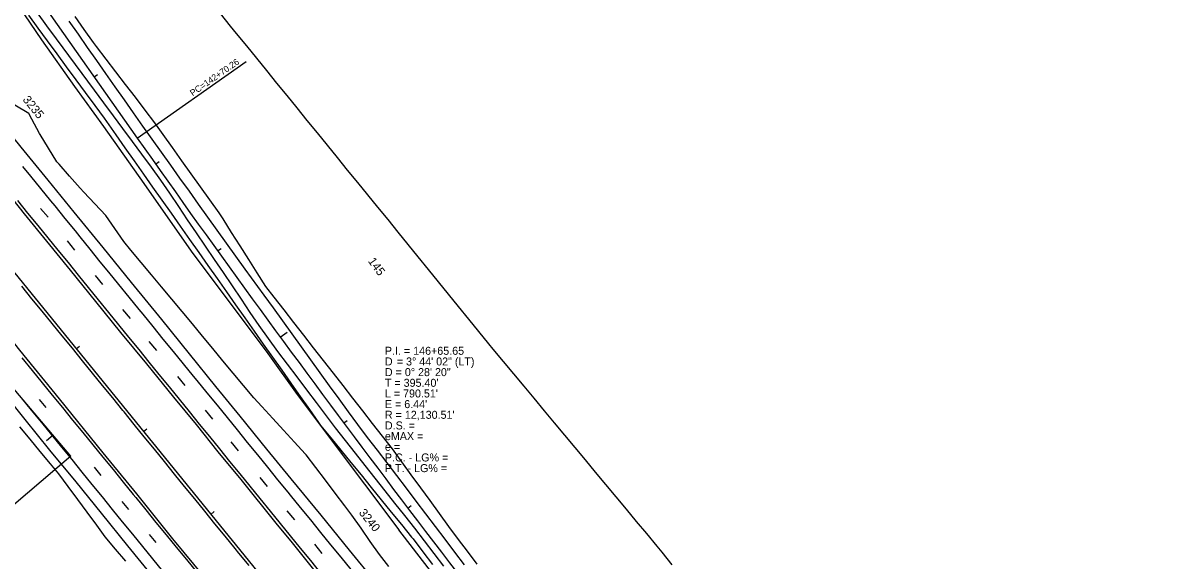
# Model space of a CAD drawing. Extents: x 2132221 to 2141942, y 535736 to 547298.
# Drawn here: x 2139996 to 2141080, y 538062 to 538566 of the extents above; entities that cross this region are included whole.
import ezdxf

# ---------------------------------------------------------------- set-up
doc = ezdxf.new("R2010")
doc.units = 0
for name, color, linetype in [('RD_EX_Driveway', 7, 'Continuous'), ('RD_EX_Fence_Other', 7, 'Continuous'), ('RD_EX_GuardRail', 7, 'Continuous'), ('RD_EX_Misc', 7, 'Continuous'), ('RD_EX_Road', 7, 'Continuous'), ('RD_EX_VEG', 7, 'Continuous'), ('RD_HC_Cl', 7, 'Continuous'), ('RD_HC_Data', 7, 'Continuous'), ('RD_HC_Data_Tic', 7, 'Continuous'), ('RD_HC_TX_Sta50', 7, 'Continuous'), ('TOPO_E_TLIML-Line', 7, 'Continuous')]:
    doc.layers.add(name, color=color, linetype=linetype)

msp = doc.modelspace()

# ---------------------------------------------------------------- linework, layer by layer
at = {"layer": 'RD_EX_Driveway'}
for points in [[(2140009.3, 538575.5), (2140018, 538563.3), (2140026.9, 538551.3), (2140062.6, 538503.2), (2140071.5, 538491.1), (2140080.4, 538479.1), (2140089.3, 538467.1), (2140098.2, 538455), (2140107.1, 538443), (2140116, 538431), (2140124.7, 538418.8), (2140133.1, 538406.4), (2140141.5, 538394), (2140149.9, 538381.6), (2140158.2, 538369.2), (2140175, 538344.4), (2140183.4, 538332), (2140191.8, 538319.6), (2140200.2, 538307.2), (2140208.6, 538294.8), (2140217, 538282.4), (2140225.5, 538270.2), (2140234.5, 538258.2), (2140243.5, 538246.3), (2140252.5, 538234.3), (2140261.5, 538222.3), (2140270.5, 538210.4), (2140288.5, 538186.5), (2140297.7, 538174.6), (2140307, 538162.9), (2140316.3, 538151.1), (2140325.5, 538139.4), (2140334.8, 538127.6), (2140344.1, 538115.9), (2140353.3, 538104.2), (2140362.6, 538092.4), (2140371.9, 538080.6), (2140380.9, 538068.7), (2140390, 538056.8)], [(2140409.6, 538058.2), (2140400.5, 538070.1), (2140391.4, 538082.1), (2140382.4, 538094), (2140373.3, 538106), (2140364.2, 538117.9), (2140355.1, 538129.8), (2140346.1, 538141.8), (2140337, 538153.7), (2140327.9, 538165.7), (2140318.8, 538177.6), (2140309.7, 538189.6), (2140300.8, 538201.6), (2140292, 538213.7), (2140283.2, 538225.9), (2140274.4, 538238.1), (2140265.7, 538250.2), (2140256.9, 538262.4), (2140248.1, 538274.6), (2140239.3, 538286.7), (2140230.6, 538298.9), (2140221.8, 538311), (2140204.2, 538335.4), (2140195.4, 538347.5), (2140186.7, 538359.7), (2140177.9, 538371.9), (2140169.2, 538384.1), (2140160.5, 538396.3), (2140151.8, 538408.5), (2140143, 538420.7), (2140134.3, 538432.9), (2140125.6, 538445.1), (2140116.9, 538457.3), (2140108.2, 538469.5), (2140099.5, 538481.8), (2140090.9, 538494), (2140082.3, 538506.3), (2140073.7, 538518.6), (2140065.1, 538530.9), (2140056.5, 538543.2), (2140047.9, 538555.5), (2140039.3, 538567.8)]]:
    msp.add_lwpolyline(points, dxfattribs=at)
at = {"layer": 'RD_EX_Fence_Other'}
msp.add_line((2140437, 537976), (2140348, 538090.8), dxfattribs=at)
for points in [[(2139980.7, 538598.3), (2140013.3, 538550.2), (2140044.2, 538506.6), (2140071.5, 538469), (2140109.3, 538415.7)], [(2140109.3, 538415.7), (2140153.5, 538352.1), (2140225.2, 538256.2)], [(2140225.2, 538256.2), (2140252.7, 538217.7), (2140316, 538133.7), (2140348, 538090.8)]]:
    msp.add_lwpolyline(points, dxfattribs=at)
at = {"layer": 'RD_EX_GuardRail'}
msp.add_lwpolyline([(2140207.8, 538057.3), (2140198.3, 538068.9), (2140194.6, 538073.3), (2140185.2, 538085), (2140175.7, 538096.6), (2140166.3, 538108.3), (2140156.8, 538119.9), (2140147.3, 538131.6), (2140137.9, 538143.2), (2140128.4, 538154.8), (2140119, 538166.5), (2140109.5, 538178.1), (2140100.1, 538189.8), (2140090.6, 538201.4), (2140089.4, 538202.8), (2140080, 538214.5), (2140070.5, 538226.1), (2140061.1, 538237.8), (2140051.6, 538249.4), (2140042.2, 538261.1), (2140032.7, 538272.7), (2140023.2, 538284.4), (2140013.8, 538296), (2140004.3, 538307.6), (2139994.9, 538319.3)], dxfattribs=at)
at = {"layer": 'RD_EX_Misc'}
for p, q in [((2140012.5, 538392.3), (2140019.5, 538383.9)), ((2140037.3, 538361.7), (2140044.3, 538353.2)), ((2140063.5, 538329.4), (2140070.5, 538320.9)), ((2140089.3, 538297.4), (2140096.3, 538289)), ((2140113.9, 538267.6), (2140121, 538259.1)), ((2140140.6, 538234.5), (2140147.6, 538226.1)), ((2140011.2, 538213), (2140017.5, 538205.5)), ((2140166.5, 538203.2), (2140173.6, 538194.8)), ((2140190.6, 538173.5), (2140197.6, 538165)), ((2140062.6, 538149.5), (2140068.9, 538141.9)), ((2140217.7, 538140.1), (2140224.7, 538131.6)), ((2140088.6, 538117.6), (2140094.8, 538110.1)), ((2140243.2, 538108.8), (2140250.2, 538100.3)), ((2140114.1, 538086.4), (2140120.4, 538078.9)), ((2140269, 538077.3), (2140276, 538068.8))]:
    msp.add_line(p, q, dxfattribs=at)
for points in [[(2139995.5, 538431.6), (2140002.9, 538422.5), (2140012.4, 538410.9), (2140021.8, 538399.2), (2140025.7, 538394.5), (2140035.2, 538382.9), (2140044.7, 538371.3), (2140049.2, 538365.6), (2140058.6, 538354), (2140068, 538342.3), (2140076, 538332.4), (2140085.5, 538320.8), (2140095, 538309.1), (2140104.5, 538297.5), (2140108.1, 538293.1), (2140117.6, 538281.4), (2140127.1, 538269.8), (2140136.6, 538258.2), (2140146.1, 538246.6), (2140155.5, 538235), (2140158.8, 538231), (2140168.2, 538219.4), (2140177.7, 538207.7), (2140187.2, 538196.1), (2140196.6, 538184.5), (2140206.1, 538172.8), (2140215.6, 538161.2), (2140225, 538149.5), (2140234.5, 538137.9), (2140244, 538126.3), (2140246.3, 538123.5), (2140255.7, 538111.8), (2140265.2, 538100.2), (2140274.7, 538088.5), (2140284.1, 538076.9), (2140293.6, 538065.3), (2140303.1, 538053.6)], [(2139990.9, 538399.6), (2140000.3, 538387.9), (2140009.8, 538376.3), (2140019.2, 538364.7), (2140028.7, 538353), (2140038.2, 538341.4), (2140047.6, 538329.7), (2140057.1, 538318.1), (2140066.5, 538306.4), (2140076, 538294.8), (2140085.5, 538283.2), (2140094.9, 538271.5), (2140104.4, 538259.9), (2140113.8, 538248.2), (2140123.3, 538236.6), (2140132.8, 538225), (2140142.2, 538213.3), (2140151.7, 538201.7), (2140161.1, 538190), (2140170.6, 538178.4), (2140180.1, 538166.8), (2140189.5, 538155.1), (2140199, 538143.5), (2140208.4, 538131.8), (2140217.9, 538120.2), (2140227.4, 538108.5), (2140236.8, 538096.9), (2140246.3, 538085.3), (2140255.7, 538073.6), (2140265.2, 538062), (2140274.7, 538050.3)], [(2139995, 538252), (2140004.5, 538240.4), (2140014, 538228.7), (2140023.4, 538217.1), (2140032.9, 538205.5), (2140042.4, 538193.8), (2140051.9, 538182.2), (2140061.3, 538170.6), (2140070.8, 538158.9), (2140080.3, 538147.3), (2140089.7, 538135.7), (2140099.2, 538124), (2140101.6, 538121.2), (2140111, 538109.5), (2140120.5, 538097.9), (2140130, 538086.3), (2140139.5, 538074.7), (2140149, 538063.1), (2140158.5, 538051.4)], [(2140127.1, 538052), (2140117.6, 538063.6), (2140108.2, 538075.3), (2140098.7, 538086.9), (2140089.2, 538098.5), (2140079.8, 538110.1), (2140070.3, 538121.8), (2140060.8, 538133.4), (2140051.3, 538145), (2140041.9, 538156.7), (2140032.4, 538168.3), (2140022.9, 538179.9), (2140013.5, 538191.6), (2140004, 538203.2), (2139994.5, 538214.8)]]:
    msp.add_lwpolyline(points, dxfattribs=at)
at = {"layer": 'RD_EX_Road'}
for points in [[(2139949.7, 538504.1), (2139971.6, 538477.2), (2139993.8, 538449.7), (2140019.3, 538418.7), (2140043.6, 538388.8), (2140070.6, 538355.7), (2140097.3, 538322.8), (2140125.6, 538288.1), (2140151.7, 538255.9), (2140176.4, 538225.3), (2140199.2, 538197.5), (2140224.2, 538166.5), (2140247, 538138.6), (2140274.9, 538104.5), (2140301.6, 538071.7), (2140325.5, 538042.3), (2140347.9, 538014.5), (2140379.1, 537976), (2140407.5, 537941.1), (2140434.4, 537908.2)], [(2139921.8, 538480), (2139946, 538450.3), (2139974.1, 538415.5), (2139997.1, 538387.2), (2140017.9, 538361.6), (2140040, 538334.4), (2140063.9, 538304.9), (2140087.4, 538275.8), (2140111.6, 538246.4), (2140136.8, 538215.3), (2140158.1, 538189.6), (2140178.4, 538164.1), (2140200, 538138), (2140232.9, 538097.2), (2140248.1, 538078.7), (2140269.5, 538052.1), (2140291.1, 538025.3), (2140312.8, 537998.5), (2140333.2, 537973.8), (2140353.8, 537948.5), (2140374.9, 537922.7), (2140401.8, 537889.8)], [(2139858, 538425.2), (2139881.2, 538396.5), (2139906.9, 538364.7), (2139937, 538327.4), (2139965.4, 538293.3), (2139992.8, 538259.4), (2140029.9, 538213.8), (2140070.8, 538163.2), (2140102.2, 538124.6), (2140136.1, 538082.6), (2140166.3, 538045.8), (2140194.7, 538011.3), (2140224.1, 537974.8), (2140258.2, 537933), (2140289.5, 537894.2), (2140331.4, 537842.8)], [(2139821.3, 538407.5), (2139844.1, 538380.3), (2139869.4, 538350.1), (2139893.2, 538321.7), (2139923, 538286.2), (2139948.2, 538255.4), (2139971.2, 538227.1), (2139997.6, 538194.4), (2140020.9, 538165.5), (2140045.4, 538135.9), (2140069.1, 538106.4), (2140094, 538075.8), (2140118.8, 538045.2), (2140147.5, 538010), (2140173, 537978.5), (2140202.7, 537942.4), (2140230.8, 537907.7), (2140252.2, 537881.4), (2140277.9, 537849.7), (2140308.2, 537812.9)]]:
    msp.add_lwpolyline(points, dxfattribs=at)
at = {"layer": 'RD_EX_VEG'}
for points in [[(2140001, 538573.4), (2140009.9, 538561.3), (2140018.7, 538549.2), (2140027.6, 538537.1), (2140036.5, 538525), (2140045.4, 538512.9), (2140054.2, 538500.9), (2140063.1, 538488.8), (2140072, 538476.7), (2140074.2, 538473.6), (2140082.9, 538461.3), (2140091.5, 538449.1), (2140100.1, 538436.8), (2140108.8, 538424.5), (2140117.4, 538412.3), (2140126, 538400), (2140134.7, 538387.7), (2140143.3, 538375.5), (2140152, 538363.2), (2140160.6, 538350.9), (2140169.2, 538338.7), (2140177.9, 538326.4), (2140186.5, 538314.1), (2140195.1, 538301.9), (2140203.8, 538289.6), (2140212.4, 538277.3), (2140221, 538265.1), (2140229.7, 538252.8), (2140238.3, 538240.5), (2140246.9, 538228.3), (2140255.6, 538216), (2140264.2, 538203.7), (2140272.8, 538191.5), (2140274.7, 538188.8), (2140284.2, 538177.2), (2140293.6, 538165.6), (2140303.1, 538153.9), (2140312.6, 538142.3), (2140322, 538130.7), (2140331.5, 538119), (2140341, 538107.4), (2140350.5, 538095.8), (2140359.9, 538084.1), (2140361.4, 538082.3), (2140370.4, 538070.4), (2140379.5, 538058.4)], [(2140421.4, 538058.8), (2140412.3, 538070.8), (2140403.8, 538081.9), (2140394.9, 538094.1), (2140386.1, 538106.2), (2140377.3, 538118.3), (2140368.5, 538130.4), (2140359.6, 538142.6), (2140350.8, 538154.7), (2140342, 538166.9), (2140332.7, 538178.7), (2140323.5, 538190.6), (2140314.3, 538202.4), (2140305.1, 538214.2), (2140295.9, 538226.1), (2140286.7, 538237.9), (2140277.4, 538249.7), (2140268.2, 538261.6), (2140259, 538273.4), (2140249.8, 538285.2), (2140240.6, 538297.1), (2140231.4, 538308.9), (2140223.4, 538319.1), (2140215.4, 538331.7), (2140207.4, 538344.4), (2140199.4, 538357.1), (2140191.4, 538369.8), (2140183.4, 538382.5), (2140179.8, 538388.2), (2140171.1, 538400.4), (2140162.3, 538412.6), (2140153.6, 538424.8), (2140144.9, 538437), (2140136.1, 538449.2), (2140127.4, 538461.4), (2140119.4, 538472.6), (2140110.3, 538484.5), (2140101.2, 538496.4), (2140092.1, 538508.4), (2140083, 538520.3), (2140073.9, 538532.2), (2140064.8, 538544.1), (2140062.1, 538547.7), (2140053.4, 538560), (2140044.8, 538572.2)], [(2140338.8, 538056.5), (2140329.9, 538067.9), (2140321.2, 538080.1), (2140312.6, 538092.3), (2140303.9, 538104.6), (2140297.6, 538113.5), (2140288.5, 538125.4), (2140279.3, 538137.3), (2140270.2, 538149.2), (2140261.1, 538161.1), (2140260.3, 538162.2), (2140250.2, 538173.2), (2140240, 538184.3), (2140229.9, 538195.3), (2140219.7, 538206.4), (2140212.1, 538214.7), (2140202.5, 538226.3), (2140192.9, 538237.8), (2140183.3, 538249.3), (2140173.7, 538260.9), (2140164.1, 538272.4), (2140154.6, 538283.9), (2140145, 538295.5), (2140135.4, 538307), (2140125.8, 538318.6), (2140116.2, 538330.1), (2140106.6, 538341.6), (2140097.1, 538353.2), (2140090.4, 538361.2), (2140081.9, 538373.5), (2140073.5, 538385.7), (2140063.2, 538396.6), (2140052.9, 538407.6), (2140049.6, 538411.2), (2140039.6, 538422.4), (2140029.7, 538433.7), (2140027.8, 538435.9), (2140019.9, 538448.7), (2140012.1, 538461.5), (2140011.4, 538462.6), (2140004.3, 538475.9), (2140001.4, 538481.3), (2139988.4, 538488.9)], [(2139992.7, 538187.6), (2140002.3, 538176), (2140011.8, 538164.4), (2140021.4, 538152.9), (2140029.1, 538143.5), (2140038, 538131.4), (2140047, 538119.3), (2140055.9, 538107.3), (2140064.8, 538095.2), (2140072.7, 538084.4), (2140082.3, 538072.9), (2140091.9, 538061.4)]]:
    msp.add_lwpolyline(points, dxfattribs=at)
at = {"layer": 'RD_HC_Cl'}
for p, q in [((2136971.6, 542041.7), (2141699.6, 536226.5)), ((2139357.9, 539516.8), (2140103, 538458.1)), ((2140040.8, 538159.9), (2139071.1, 539303.6))]:
    msp.add_line(p, q, dxfattribs=at)
msp.add_arc((2150022.6, 545440.3), 12130.5, 215.14072, 218.87453, dxfattribs=at)
at = {"layer": 'RD_HC_Data'}
for p, q in [((2140103, 538458.1), (2140205, 538529.9)), ((2140040.8, 538159.9), (2139935.7, 538070.8))]:
    msp.add_line(p, q, dxfattribs=at)
at = {"layer": 'RD_HC_Data_Tic'}
for p, q in [((2140062.6, 538515.6), (2140065.9, 538517.9)), ((2140120.2, 538433.8), (2140123.4, 538436.1)), ((2140178.3, 538352.4), (2140181.5, 538354.8)), ((2140237, 538271.5), (2140243.5, 538276.3)), ((2140045.8, 538260.6), (2140048.9, 538263.2)), ((2140108.8, 538183), (2140111.9, 538185.6)), ((2140296.5, 538191.1), (2140299.7, 538193.5)), ((2140024.1, 538179.5), (2140018, 538174.4)), ((2140171.9, 538105.4), (2140175, 538108)), ((2140356.6, 538111.2), (2140359.7, 538113.6))]:
    msp.add_line(p, q, dxfattribs=at)
at = {"layer": 'TOPO_E_TLIML-Line'}
msp.add_lwpolyline([(2140604.1, 538058.2), (2140594.7, 538069.8), (2140589.9, 538075.7), (2140580.3, 538087.3), (2140570.8, 538098.8), (2140561.2, 538110.4), (2140551.6, 538121.9), (2140542, 538133.4), (2140532.4, 538145), (2140522.8, 538156.5), (2140513.2, 538168), (2140503.6, 538179.6), (2140494, 538191.1), (2140484.5, 538202.6), (2140474.9, 538214.2), (2140465.3, 538225.7), (2140455.7, 538237.2), (2140446.1, 538248.8), (2140436.5, 538260.3), (2140432.4, 538265.2), (2140423, 538276.9), (2140413.5, 538288.5), (2140404, 538300.2), (2140394.6, 538311.8), (2140385.1, 538323.4), (2140375.7, 538335.1), (2140366.2, 538346.7), (2140356.8, 538358.4), (2140347.3, 538370), (2140337.9, 538381.7), (2140328.4, 538393.3), (2140318.9, 538405), (2140309.5, 538416.6), (2140300, 538428.2), (2140290.6, 538439.9), (2140281.1, 538451.5), (2140271.7, 538463.2), (2140262.2, 538474.8), (2140252.8, 538486.5), (2140243.3, 538498.1), (2140233.8, 538509.8), (2140224.4, 538521.4), (2140214.9, 538533), (2140205.5, 538544.7), (2140196, 538556.3), (2140190.4, 538563.2), (2140180.9, 538574.9)], dxfattribs=at)

# ---------------------------------------------------------------- texts
at = {"layer": 'RD_HC_Data'}
msp.add_text('PC=142+70.26', height=6, rotation=35.1407, dxfattribs=at).set_placement((2140155, 538497.2))
for s, p in [('P.I. = 146+65.65', (2140335, 538255)), ('D', (2140335, 538245)), ('    = 3%%d 44\' 02" (LT)', (2140335, 538245)), ('D = 0%%d 28\' 20"', (2140335, 538235)), ("T = 395.40'", (2140335, 538225)), ("L = 790.51'", (2140335, 538215)), ("E = 6.44'", (2140335, 538205)), ("R = 12,130.51'", (2140335, 538195)), ('D.S. = ', (2140335, 538185)), ('eMAX = ', (2140335, 538175)), ('e = ', (2140335, 538165)), ('P.C. - LG% = ', (2140335, 538155)), ('P.T. - LG% = ', (2140335, 538145))]:
    msp.add_text(s, height=7.5, dxfattribs=at).set_placement(p)
at = {"layer": 'RD_HC_TX_Sta50'}
for s, rotation, p in [('3235', 309.1127, (2139995.2, 538494)), ('145', 306.2259, (2140318.8, 538342.7)), ('3240', 309.1127, (2140310.1, 538106.7))]:
    msp.add_text(s, height=8, rotation=rotation, dxfattribs=at).set_placement(p)

doc.saveas('drawing.dxf')
